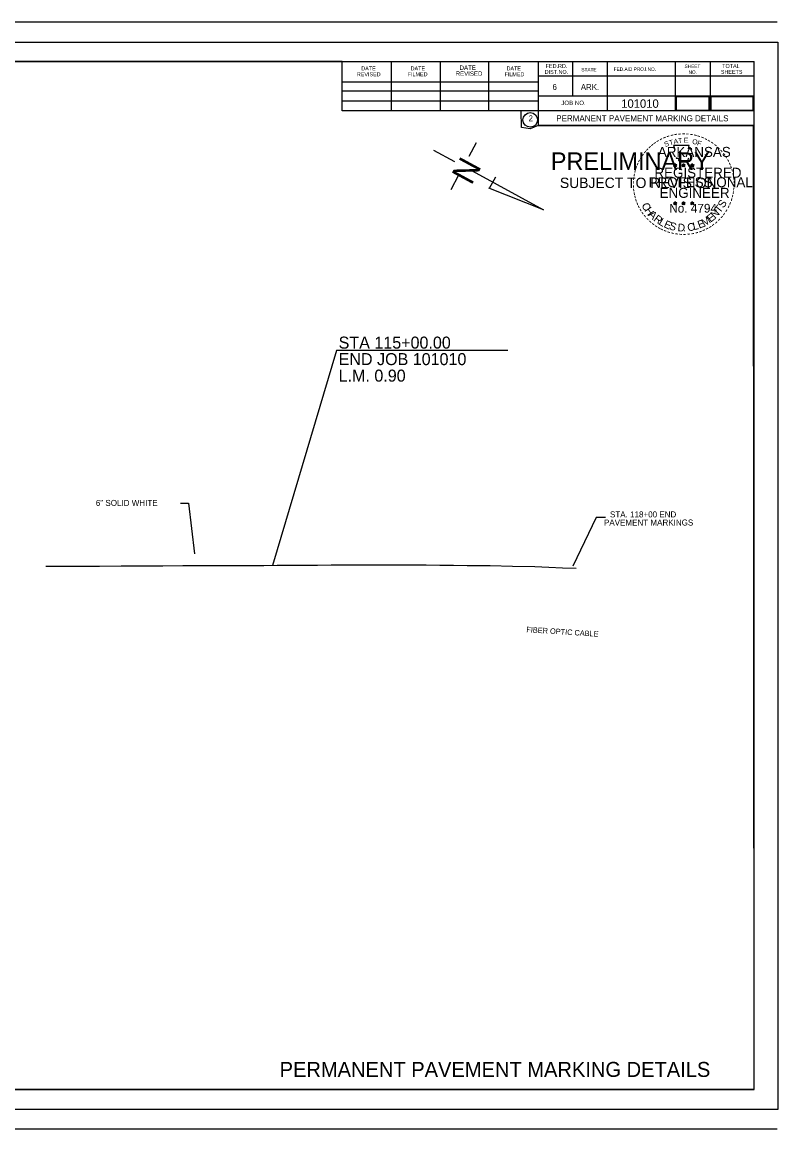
# Model space of a CAD drawing. Extents: x 9844 to 11605, y 9961 to 11067.
# Drawn here: x 10850 to 11605, y 9961 to 11067 of the extents above; entities that cross this region are included whole.
import ezdxf

# ---------------------------------------------------------------- set-up
doc = ezdxf.new("R2010")
doc.units = 0
for name, color, linetype in [('C-PSVP', 7, 'Continuous'), ('GREEN_TXT', 7, 'Continuous'), ('R_Border Notes', 7, 'Continuous'), ('R_Horz Alg', 7, 'Continuous'), ('S_FIBER_OPTIC_CABLE_ANNOT', 7, 'Continuous'), ('S_PAVEMENT_CROWN', 7, 'Continuous'), ('SEAL-INFO', 7, 'Continuous'), ('SIGNATURE', 7, 'Continuous'), ('STA Text', 7, 'Continuous'), ('TEXT', 7, 'Continuous'), ('White Markings DETOUR', 7, 'Continuous')]:
    doc.layers.add(name, color=color, linetype=linetype)

msp = doc.modelspace()

# ---------------------------------------------------------------- linework, layer by layer
for p, q in [((11303.5, 10946.1), (11296.1, 10932.5)), ((11260.8, 10938.8), (11281.8, 10927.4)), ((11299.2, 10918), (11370.7, 10879.2)), ((11285.8, 10913.6), (11278, 10899.1)), ((11322.6, 10911.7), (11316.4, 10900.3)), ((11370.7, 10879.2), (11316, 10900.6))]:
    msp.add_line(p, q)
at = {"layer": 'C-PSVP'}
for p, q in [((11500.3, 10924), (11502.1, 10923.5)), ((11500.3, 10924), (11501.6, 10923.8)), ((11500.3, 10924), (11501.5, 10923.4)), ((11501, 10922), (11502.1, 10923.5)), ((11501, 10922), (11501.6, 10923.2)), ((11501, 10922), (11502, 10923.1)), ((11502.1, 10925.3), (11501.8, 10924.1)), ((11503.1, 10922), (11502, 10923.1)), ((11502.1, 10923.5), (11502.1, 10925.3)), ((11502.1, 10925.3), (11502.3, 10924.1)), ((11503.8, 10924), (11502.1, 10923.5)), ((11503.1, 10922), (11502.1, 10923.5)), ((11503.8, 10924), (11502.4, 10923.8)), ((11503.1, 10922), (11502.4, 10923.5)), ((11503.8, 10924), (11502.8, 10923.5)), ((11508.7, 10924), (11510.4, 10923.5)), ((11508.7, 10924), (11509.9, 10923.8)), ((11508.7, 10924), (11509.8, 10923.4)), ((11509.3, 10922), (11510.4, 10923.5)), ((11509.3, 10922), (11510, 10923.2)), ((11509.3, 10922), (11510.4, 10923.1)), ((11510.4, 10925.3), (11510.2, 10924.1)), ((11510.4, 10923.5), (11510.4, 10925.3)), ((11510.4, 10925.3), (11510.6, 10924.1)), ((11512.1, 10924), (11510.4, 10923.5)), ((11511.5, 10922), (11510.4, 10923.5)), ((11511.5, 10922), (11510.4, 10923.1)), ((11512.1, 10924), (11510.7, 10923.8)), ((11511.5, 10922), (11510.8, 10923.5)), ((11512.1, 10924), (11511.1, 10923.5)), ((11517.5, 10924), (11519.2, 10923.4)), ((11517.5, 10924), (11518.7, 10923.8)), ((11517.5, 10924), (11518.7, 10923.4)), ((11518.1, 10921.9), (11519.2, 10923.4)), ((11518.1, 10921.9), (11518.8, 10923.2)), ((11518.1, 10921.9), (11519.2, 10923)), ((11519.2, 10925.3), (11519, 10924)), ((11519.2, 10923.4), (11519.2, 10925.3)), ((11519.2, 10925.3), (11519.5, 10924)), ((11521, 10924), (11519.2, 10923.4)), ((11520.3, 10921.9), (11519.2, 10923.4)), ((11520.3, 10921.9), (11519.2, 10923)), ((11521, 10924), (11519.5, 10923.7)), ((11520.3, 10921.9), (11519.6, 10923.4)), ((11521, 10924), (11519.9, 10923.5)), ((11500.3, 10886.2), (11502, 10885.6)), ((11500.3, 10886.2), (11501.6, 10886)), ((11500.3, 10886.2), (11501.5, 10885.6)), ((11501, 10884.1), (11502, 10885.6)), ((11501, 10884.1), (11501.6, 10885.4)), ((11501, 10884.1), (11502, 10885.2)), ((11502, 10887.4), (11501.8, 10886.2)), ((11502, 10885.6), (11502, 10887.4)), ((11502, 10887.4), (11502.3, 10886.2)), ((11503.8, 10886.2), (11502, 10885.6)), ((11503.1, 10884.1), (11502, 10885.6)), ((11503.1, 10884.1), (11502, 10885.2)), ((11503.8, 10886.2), (11502.3, 10885.9)), ((11503.1, 10884.1), (11502.4, 10885.6)), ((11503.8, 10886.2), (11502.7, 10885.7)), ((11508.6, 10886.2), (11510.4, 10885.6)), ((11508.6, 10886.2), (11509.9, 10886)), ((11508.6, 10886.2), (11509.8, 10885.6)), ((11509.3, 10884.1), (11510.4, 10885.6)), ((11509.3, 10884.1), (11509.9, 10885.4)), ((11509.3, 10884.1), (11510.4, 10885.2)), ((11510.4, 10887.4), (11510.2, 10886.2)), ((11510.4, 10885.6), (11510.4, 10887.4)), ((11510.4, 10887.4), (11510.6, 10886.2)), ((11512.1, 10886.2), (11510.4, 10885.6)), ((11511.4, 10884.1), (11510.4, 10885.6)), ((11511.4, 10884.1), (11510.4, 10885.2)), ((11512.1, 10886.2), (11510.7, 10885.9)), ((11511.4, 10884.1), (11510.8, 10885.6)), ((11512.1, 10886.2), (11511.1, 10885.7)), ((11517.5, 10886.1), (11519.2, 10885.6)), ((11517.5, 10886.1), (11518.7, 10885.9)), ((11517.5, 10886.1), (11518.7, 10885.5)), ((11518.1, 10884.1), (11519.2, 10885.6)), ((11518.1, 10884.1), (11518.8, 10885.3)), ((11518.1, 10884.1), (11519.2, 10885.2)), ((11519.2, 10887.4), (11519, 10886.1)), ((11519.2, 10885.6), (11519.2, 10887.4)), ((11519.2, 10887.4), (11519.5, 10886.1)), ((11520.9, 10886.1), (11519.2, 10885.6)), ((11520.3, 10884.1), (11519.2, 10885.6)), ((11520.3, 10884.1), (11519.2, 10885.2)), ((11520.9, 10886.1), (11519.5, 10885.9)), ((11520.3, 10884.1), (11519.6, 10885.5)), ((11520.9, 10886.1), (11519.9, 10885.6))]:
    msp.add_line(p, q, dxfattribs=at)
for points in [[(11500.5, 10943.4), (11501.9, 10939.3)], [(11518.1, 10938.8), (11518.8, 10940.2), (11515.4, 10940.1), (11516.1, 10943.4), (11500.5, 10943.4)], [(11503, 10931.3), (11503, 10930.9), (11505.8, 10930.8), (11505.5, 10928.4), (11514.9, 10928.4), (11515.9, 10931.1)], [(11502.1, 10925.3), (11503.1, 10922), (11500.3, 10924), (11503.8, 10924), (11501, 10922), (11502.1, 10925.3)], [(11510.4, 10925.3), (11511.5, 10922), (11508.7, 10924), (11512.1, 10924), (11509.3, 10922), (11510.4, 10925.3)], [(11519.2, 10925.3), (11520.3, 10921.9), (11517.5, 10924), (11521, 10924), (11518.1, 10921.9), (11519.2, 10925.3)], [(11502, 10887.4), (11503.1, 10884.1), (11500.3, 10886.2), (11503.8, 10886.2), (11501, 10884.1), (11502, 10887.4)], [(11510.4, 10887.4), (11511.4, 10884.1), (11508.6, 10886.2), (11512.1, 10886.2), (11509.3, 10884.1), (11510.4, 10887.4)], [(11519.2, 10887.4), (11520.3, 10884.1), (11517.5, 10886.1), (11520.9, 10886.1), (11518.1, 10884.1), (11519.2, 10887.4)]]:
    msp.add_lwpolyline(points, dxfattribs=at)
for centre, radius in [((11502, 10923.5), 0.861), ((11502, 10923.5), 0.723), ((11502, 10923.5), 0.579), ((11502, 10923.5), 0.495), ((11502, 10923.5), 0.374), ((11502, 10923.5), 0.248), ((11502, 10923.5), 0.148), ((11510.4, 10923.5), 0.861), ((11510.4, 10923.5), 0.723), ((11510.4, 10923.5), 0.579), ((11510.4, 10923.5), 0.495), ((11510.4, 10923.5), 0.374), ((11510.4, 10923.5), 0.248), ((11510.4, 10923.5), 0.148), ((11519.2, 10923.4), 0.861), ((11519.2, 10923.4), 0.723), ((11519.2, 10923.4), 0.579), ((11519.2, 10923.4), 0.495), ((11519.2, 10923.4), 0.374), ((11519.2, 10923.4), 0.248), ((11519.2, 10923.4), 0.148), ((11502, 10885.6), 0.861), ((11502, 10885.6), 0.723), ((11502, 10885.6), 0.579), ((11502, 10885.6), 0.495), ((11502, 10885.6), 0.374), ((11502, 10885.6), 0.248), ((11502, 10885.6), 0.148), ((11510.4, 10885.6), 0.861), ((11510.4, 10885.6), 0.723), ((11510.4, 10885.6), 0.579), ((11510.4, 10885.6), 0.495), ((11510.4, 10885.6), 0.374), ((11510.4, 10885.6), 0.248), ((11510.4, 10885.6), 0.148), ((11519.2, 10885.6), 0.861), ((11519.2, 10885.6), 0.723), ((11519.2, 10885.6), 0.579), ((11519.2, 10885.6), 0.495), ((11519.2, 10885.6), 0.374), ((11519.2, 10885.6), 0.248), ((11519.2, 10885.6), 0.148)]:
    msp.add_circle(centre, radius, dxfattribs=at)
at = {"layer": 'GREEN_TXT'}
for p, q in [((11603.9, 11066.7), (9843.9, 11066.7)), ((10000, 11027.3), (11580.9, 11027.3)), ((11169.6, 10977.9), (11169.6, 11027.3)), ((11218.9, 10977.9), (11218.9, 11026.3)), ((11267.7, 10977.9), (11267.7, 11026.3)), ((11316.1, 10977.9), (11316.1, 11026.3)), ((11365.4, 11027.3), (11365.4, 10963.3)), ((11399.6, 11027.3), (11399.6, 10992.6)), ((11434.3, 11027.3), (11434.3, 10977.9)), ((11502.2, 11027.3), (11502.2, 10977.9)), ((11536.9, 11027.3), (11536.9, 10977.9)), ((11580.9, 10000), (11580.9, 11027.3)), ((11169.6, 11007.2), (11365.4, 11007.2)), ((11580.9, 11012.6), (11365.4, 11012.6)), ((11580.9, 11012.7), (11580.9, 11012.7)), ((11169.6, 10997.9), (11365.4, 10997.9)), ((11169.6, 10988.2), (11365.4, 10988.2)), ((11580.9, 10992.6), (11365.4, 10992.6)), ((11580.9, 10977.9), (11169.6, 10977.9)), ((11365.4, 10963.3), (11580.9, 10963.3)), ((11580.9, 10000), (10000, 10000)), ((9843.9, 9960.6), (11603.9, 9960.6))]:
    msp.add_line(p, q, dxfattribs=at)
msp.add_circle((11357.3, 10969), 7.33, dxfattribs=at)
at = {"layer": 'R_Horz Alg'}
msp.add_lwpolyline([(11537.7, 10978.6), (11580.1, 10978.6), (11580.1, 10991.9), (11537.7, 10991.9)], close=True, dxfattribs=at)
at = {"layer": 'S_PAVEMENT_CROWN'}
msp.add_lwpolyline([(10873.5, 10522.9), (10886.9, 10523), (10900.2, 10523), (10913.6, 10523.1), (10927, 10523.1), (10948.8, 10523.2), (10970.5, 10523.2), (10990.5, 10523.3), (11010.4, 10523.5), (11030.4, 10523.6), (11050.3, 10523.7), (11070.8, 10523.7), (11091.3, 10523.8), (11104.7, 10523.9), (11118.1, 10524), (11131.5, 10524), (11145, 10524.1), (11158.6, 10524.2), (11172.2, 10524.2), (11185.8, 10524.3), (11199.4, 10524.3), (11212.9, 10524.3), (11226.3, 10524.3), (11239.8, 10524.2), (11253.3, 10524.2), (11267, 10524.1), (11280.7, 10524), (11294.4, 10523.8), (11308.1, 10523.7), (11317.4, 10523.6), (11339.7, 10523), (11362.1, 10522.5), (11375.8, 10521.9), (11389.6, 10521.4), (11403.3, 10520.9)], dxfattribs=at)
at = {"layer": 'SEAL-INFO'}
for points in [[(9938, 11046.8), (11604.7, 11046.8), (11604.7, 9980.1), (9938, 9980.1)], [(10000, 10000), (11580.9, 10000), (11580.3, 10963.3), (11365.4, 10963.3), (11357.3, 10959.9), (11348.5, 10961.4), (11348.3, 10977.9), (11169.6, 10977.9), (11169.6, 11027.3), (10000, 11027.3)], [(10000, 10000), (11580.9, 10000), (11580.3, 10963.3), (11365.4, 10963.3), (11357.3, 10959.9), (11348.5, 10961.4), (11348.3, 10977.9), (11169.6, 10977.9), (11169.6, 11027.3), (10000, 11027.3)], [(10000, 10000), (11580.9, 10000), (11580.3, 10963.3), (11365.4, 10963.3), (11357.3, 10959.9), (11348.5, 10961.4), (11348.3, 10977.9), (11169.6, 10977.9), (11169.6, 11027.3), (10000, 11027.3)]]:
    msp.add_lwpolyline(points, close=True, dxfattribs=at)
at = {"layer": 'STA Text'}
msp.add_lwpolyline([(11334.9, 10738.6), (11163.8, 10738.6), (11100, 10523.5)], dxfattribs=at)
at = {"layer": 'TEXT'}
for points in [[(11008, 10586), (11015.9, 10586), (11022.1, 10535.3)], [(11432.4, 10571.6), (11423.2, 10571.6), (11400, 10523)]]:
    msp.add_lwpolyline(points, dxfattribs=at)
at = {"layer": 'White Markings DETOUR'}
msp.add_lwpolyline([(11503.2, 10978.6), (11535.9, 10978.6), (11535.9, 10991.9), (11503.2, 10991.9)], close=True, dxfattribs=at)

# ---------------------------------------------------------------- texts
msp.add_text('N', height=23.3, rotation=241.4896).set_placement((11288.7, 10933.8))
at = {"layer": 'C-PSVP'}
for s, height, rotation, p in [('-', 8, 28.7918, (11487.9, 10946.1)), ('-', 8, 24.3072, (11491.1, 10947.7)), ('-', 8, 19.1761, (11494.3, 10949.1)), ('-', 8, 13.6302, (11498, 10950.3)), ('-', 8, 10.2193, (11501.4, 10951.1)), ('T', 5, 6.0228, (11505.2, 10945.6)), ('-', 8, 5.8968, (11505, 10951.6)), ('-', 8, 0.1862, (11508.9, 10952)), ('E', 5, 0.8323, (11510.8, 10946.1)), ('-', 8, 357.743, (11512.5, 10951.9)), ('-', 8, 352.1617, (11516.2, 10951.6)), ('-', 8, 347.2049, (11519.8, 10951.1)), ('-', 8, 342.3362, (11523, 10950.3)), ('-', 8, 337.8551, (11526.7, 10949.2)), ('-', 8, 334.1211, (11529.8, 10947.8)), ('-', 8, 48.4231, (11475.3, 10935.9)), ('-', 8, 42.9622, (11477.5, 10938.3)), ('-', 8, 38.9507, (11479.7, 10940.4)), ('-', 8, 36.2317, (11482, 10942.3)), ('-', 8, 34.0636, (11484.9, 10944.3)), ('S', 5, 21.594, (11492.3, 10941.8)), ('T', 5, 16.4036, (11496.9, 10943.5)), ('A', 5, 11.2132, (11501, 10944.7)), ('O', 5, 350.4515, (11518.8, 10945.1)), ('F', 5, 340.0707, (11523.5, 10943.9)), ('-', 8, 329.6409, (11532.7, 10946.4)), ('-', 8, 325.8627, (11535.9, 10944.6)), ('-', 8, 320.5297, (11539, 10942.5)), ('-', 8, 315.5786, (11542, 10940)), ('-', 8, 62.8713, (11468, 10925)), ('-', 8, 58.0706, (11469.6, 10928)), ('-', 8, 54.2325, (11471.2, 10930.7)), ('-', 8, 50.6142, (11473.2, 10933.5)), ('-', 8, 309.8797, (11544.8, 10937.3)), ('-', 8, 306.6522, (11547.5, 10934.3)), ('-', 7, 303.6753, (11549.9, 10931.4)), ('-', 8, 299.6684, (11551.5, 10928.4)), ('-', 8, 75.461, (11464.6, 10915.2)), ('-', 8, 72.3945, (11465.6, 10918.8)), ('-', 8, 67.7743, (11466.7, 10921.9)), ('-', 8, 294.6628, (11553.1, 10925.3)), ('-', 8, 290.5728, (11554.4, 10922.5)), ('-', 8, 285.1233, (11555.6, 10919.6)), ('-', 8, 89.0622, (11463.4, 10904.7)), ('-', 8, 85.1863, (11463.6, 10908.2)), ('-', 8, 81.2013, (11464, 10911.6)), ('-', 8, 280.5493, (11556.6, 10915.9)), ('-', 8, 276.5962, (11557.4, 10912)), ('-', 8, 274.3301, (11557.7, 10908.4)), ('-', 8, 94.1959, (11463.6, 10901.1)), ('-', 8, 98.9479, (11464, 10897.7)), ('-', 8, 101.7149, (11464.7, 10894.1)), ('-', 8, 260.9953, (11557.4, 10898.6)), ('-', 8, 263.5172, (11557.7, 10901.9)), ('-', 8, 269.9407, (11557.8, 10905.2)), ('-', 8, 105.4578, (11465.5, 10891.1)), ('-', 8, 109.0874, (11466.5, 10887.9)), ('-', 8, 114.0643, (11467.8, 10884.9)), ('C', 7.7, 296.9133, (11468.2, 10883.9)), ('T', 7.7, 51.5114, (11546.8, 10875.1)), ('S', 7.7, 57.878, (11550.5, 10880.3)), ('-', 8, 247.8887, (11554.8, 10888.3)), ('-', 8, 255.7626, (11555.9, 10891.8)), ('-', 8, 255.7626, (11556.8, 10895.3)), ('-', 8, 115.7289, (11469.3, 10881.9)), ('-', 8, 120.4471, (11471.1, 10878.9)), ('-', 8, 125.8934, (11473.1, 10876.1)), ('-', 8, 130.7181, (11475.4, 10873.4)), ('H', 7.7, 303.2799, (11471.1, 10878.7)), ('A', 7.7, 316.013, (11474.8, 10873.6)), ('R', 7.7, 322.3796, (11479.9, 10868.7)), ('E', 7.7, 38.7783, (11537.6, 10866.2)), ('N', 7.7, 45.1449, (11542, 10869.9)), ('-', 8, 231.2538, (11547.4, 10875.3)), ('-', 8, 233.8452, (11549.5, 10878.1)), ('-', 8, 239.0712, (11551.5, 10881.4)), ('-', 8, 244.6197, (11553.5, 10885.1)), ('-', 8, 134.2238, (11478, 10870.6)), ('-', 8, 138.9338, (11480.7, 10868.3)), ('-', 8, 144.6463, (11483.4, 10866.3)), ('-', 8, 148.0898, (11486.2, 10864.4)), ('-', 8, 151.5704, (11489.1, 10862.8)), ('L', 7.7, 328.7461, (11485, 10864.9)), ('E', 7.7, 335.1127, (11490.1, 10862.1)), ('S', 7.7, 341.4792, (11495.4, 10860)), ('D', 7.7, 354.2124, (11504.2, 10857.9)), ('C', 7.7, 6.9455, (11514.7, 10857.7)), ('L', 7.7, 13.3121, (11520.6, 10858.7)), ('E', 7.7, 19.6786, (11526.1, 10860.3)), ('M', 7.7, 32.4117, (11531.2, 10862.1)), ('-', 8, 212.2491, (11537, 10865.6)), ('-', 8, 215.7363, (11539.6, 10867.6)), ('-', 8, 221.0851, (11542.4, 10869.9)), ('-', 8, 225.7653, (11545, 10872.5)), ('-', 8, 154.6002, (11491.7, 10861.6)), ('-', 8, 158.5612, (11494.9, 10860.3)), ('-', 8, 162.7983, (11498.3, 10859.2)), ('-', 8, 167.5555, (11501.9, 10858.4)), ('-', 8, 173.1155, (11505.7, 10857.9)), ('-', 8, 176.5183, (11509.5, 10857.6)), ('-', 8, 181.5918, (11513.2, 10857.7)), ('.', 7.7, 0.5789, (11510.1, 10857.5)), ('-', 8, 185.8167, (11517.2, 10858.1)), ('-', 8, 191.2858, (11520.9, 10858.7)), ('-', 8, 195.4743, (11524.6, 10859.7)), ('-', 8, 200.7184, (11528, 10860.9)), ('-', 8, 204.2516, (11531, 10862.3)), ('-', 8, 207.3568, (11534.2, 10863.9))]:
    msp.add_text(s, height=height, rotation=rotation, dxfattribs=at).set_placement(p)
for s, height, p in [('ARKANSAS', 10, (11484.8, 10932)), ('REGISTERED', 10, (11481.4, 10911.2)), ('PROFESSIONAL', 10, (11475.6, 10901.7)), ('ENGINEER', 10, (11486.6, 10891.1)), ('No. 4794', 8.78, (11496.2, 10876.3))]:
    msp.add_text(s, height=height, dxfattribs=at).set_placement(p)
at = {"layer": 'GREEN_TXT'}
for s, height, p in [('DATE', 3.91, (11188.6, 11018.5)), ('DATE', 3.91, (11237.9, 11018.5)), ('REVISED', 4.4, (11282.9, 11013.1)), ('DATE', 4.4, (11286.8, 11019)), ('DATE', 3.91, (11333.7, 11018.5)), ('DIST.NO.', 3.91, (11371.8, 11015)), ('FED.RD.', 3.91, (11372.8, 11020.9)), ('STATE', 3.42, (11408.4, 11017.5)), ('FED.AID PROJ.NO.', 3.42, (11440.7, 11018)), ('SHEET', 3.42, (11511.5, 11020.9)), ('NO.', 3.42, (11515.4, 11015)), ('SHEETS', 3.91, (11547.7, 11015)), ('TOTAL', 3.91, (11549.1, 11020.9)), ('REVISED', 3.91, (11184.2, 11012.6)), ('FILMED', 3.91, (11235, 11012.6)), ('FILMED', 3.91, (11331.7, 11012.6)), ('6', 5.86, (11379.6, 10998.9)), ('ARK.', 5.86, (11407.9, 10998.9)), ('JOB NO.', 4.4, (11388.4, 10983.8)), ('2', 5.86, (11355.7, 10967.7)), ('PERMANENT PAVEMENT MARKING DETAILS', 15, (11107, 10012.5))]:
    msp.add_text(s, height=height, dxfattribs=at).set_placement(p)
at = {"layer": 'R_Border Notes'}
for s, height, p in [('101010', 8.4, (11448.2, 10981.1)), ('PERMANENT PAVEMENT MARKING DETAILS', 6, (11383.3, 10967.6))]:
    msp.add_text(s, height=height, dxfattribs=at).set_placement(p)
at = {"layer": 'S_FIBER_OPTIC_CABLE_ANNOT'}
msp.add_text('FIBER OPTIC CABLE', height=5.5, rotation=356.3184, dxfattribs=at).set_placement((11353.3, 10457))
at = {"layer": 'SIGNATURE'}
for s, height, p in [('PRELIMINARY', 17.5, (11377.9, 10919)), ('SUBJECT TO REVISION', 10.376, (11387, 10900.9))]:
    msp.add_text(s, height=height, dxfattribs=at).set_placement(p)
at = {"layer": 'STA Text'}
for s, p in [('STA 115+00.00', (11166, 10740.4)), ('END JOB 101010', (11166, 10723.9)), ('L.M. 0.90', (11166, 10707.4))]:
    msp.add_text(s, height=12, dxfattribs=at).set_placement(p)
at = {"layer": 'TEXT'}
for s, p in [('6" SOLID WHITE', (10923.5, 10583.2)), ('STA. 118+00 END', (11437, 10571.7)), ('PAVEMENT MARKINGS', (11431, 10563.6))]:
    msp.add_text(s, height=6, dxfattribs=at).set_placement(p)

doc.saveas('drawing.dxf')
